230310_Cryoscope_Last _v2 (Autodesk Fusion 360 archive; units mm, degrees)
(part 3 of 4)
extrude "Extrude4" cut sketch "Sketch3" profile of L5 L6 L7 L8 against normal blind 100
sketch "Sketch4" plane through (0, 0, 1) normal (0, 0, -1) x axis (1, 0, 0)
  line L1 (0.5, -31.5) -> (23.5, -31.5)
  line L2 (0.5, -0.5) -> (0.5, -31.5)
  line L3 (23.5, -0.5) -> (0.5, -0.5)
  line L4 (23.5, -31.5) -> (23.5, -0.5)
  line L5 (-4, -63.5) -> (-4, 31.5)
  line L6 (28, -63.5) -> (-4, -63.5)
  line L7 (28, 31.5) -> (28, -63.5)
  line L8 (-4, 31.5) -> (28, 31.5)
  line L9 (23.5, -31.5) -> (0.5, -0.5)
  line L10 (23.5, -0.5) -> (0.5, -31.5)
  line L11 (24.25, -32.25) -> (-0.25, -32.25)
  line L12 (24.25, 0.25) -> (24.25, -32.25)
  line L13 (-0.25, 0.25) -> (24.25, 0.25)
  line L14 (-0.25, -32.25) -> (-0.25, 0.25)
  line L15 (24.25, 0.25) -> (-0.25, -32.25)
  line L16 (-0.25, 0.25) -> (24.25, -32.25)
  point P4 (0.5, -0.5)
  point P10 (0.5, -0.5)
  point P2 (23.5, -31.5)
  point P11 (23.5, -31.5)
  point P3 (0.5, -31.5)
  point P12 (0.5, -31.5)
  point P5 (23.5, -0.5)
  point P13 (23.5, -0.5)
  point P18 (12, -16)
  point P16 (24.25, 0.25)
  point P17 (-0.25, 0.25)
  point P15 (24.25, -32.25)
  coincident P4 P10
  coincident P2 P11
  coincident P3 P12
  coincident P5 P13
  horizontal L11
  perpendicular L11 L12
  parallel L11 L13
  parallel L12 L14
  coincident L15 P18
  coincident L16 P18
  midpoint L10 P18
  dimension "d15" distance P16 P17 = 24.5 (= "24 mm + 0.5 mm")
  dimension "d16" distance P15 P16 = 32.5
extrude "Extrude5" cut sketch "Sketch4" profile of L1 L2 L3 L4 L11 L12 L13 L14 against normal blind 0.5
move "Move1"
sketch "Sketch5" plane through (0, 63.5, 0) normal (0, 1, 0) x axis (-1, 0, 0)
  line L1 (-2.1851, -13.9322) -> (-24.8125, 8.6952)
  line L2 (-0.0638, -11.8109) -> (-2.1851, -13.9322)
  line L3 (-22.6912, 10.8165) -> (-0.0638, -11.8109)
  line L4 (-24.8125, 8.6952) -> (-22.6912, 10.8165)
  line L5 (-2.1851, -11.8109) -> (-0.0638, -11.8109)
  line L6 (-2.1851, -13.9322) -> (-2.1851, -11.8109)
  line L7 (-0.0638, -13.9322) -> (-2.1851, -13.9322)
  line L8 (-0.0638, -11.8109) -> (-0.0638, -13.9322)
  line L9 (-2.1851, -11.8109) -> (-0.0638, -11.8109)
  line L10 (-2.1851, -9.6896) -> (-2.1851, -11.8109)
  line L11 (-0.0638, -9.6896) -> (-2.1851, -9.6896)
  line L12 (-0.0638, -11.8109) -> (-0.0638, -9.6896)
  point P3 (-2.1851, -13.9322)
  point P8 (-2.1851, -13.9322)
  point P4 (-0.0638, -11.8109)
  point P6 (-0.0638, -11.8109)
  point P11 (-2.1851, -9.6896)
  horizontal L5
  vertical L6
  horizontal L7
  vertical L8
  coincident P3 P8
  coincident P4 P6
  horizontal L9
  vertical L10
  horizontal L11
  vertical L12
  coincident L3 P11
extrude "Extrude6" add sketch "Sketch5" profile of L2 L3 L7 L8 L11 L12 against normal blind 95
extrude "Extrude7" add of existing geometry blind 7.788 (= "10 mm - 2.212 mm")
extrude "Extrude8" add of existing geometry blind 0.91
extrude "Extrude9" cut of existing geometry blind -2
sketch "Sketch6" plane through (0, 0, -13.9322) normal (0, 0, -1) x axis (1, 0, 0)
  line L1 (2.1851, -63.5) -> (-8.6342, -63.5)
  line L2 (2.1851, 31.5) -> (2.1851, -63.5)
  line L3 (-8.6342, 31.5) -> (2.1851, 31.5)
  line L4 (-8.6342, -63.5) -> (-8.6342, 31.5)
  line L5 (10.0341, 31.5) -> (-8.6342, 31.5)
  line L6 (10.0341, -63.5) -> (10.0341, 31.5)
  line L7 (-8.6342, -63.5) -> (10.0341, -63.5)
  line L8 (-8.6342, 31.5) -> (-8.6342, -63.5)
  point P5 (-8.6342, 31.5)
  point P6 (-8.6342, 31.5)
  horizontal L5
  vertical L6
  horizontal L7
  vertical L8
  coincident P5 P6
extrude "Extrude10" cut sketch "Sketch6" against normal blind 1
extrude "Extrude11" cut of existing geometry blind -3
sketch "Sketch7" plane through (0, 0, -12.9322) normal (0, 0, -1) x axis (1, 0, 0)
  line L1 (-5.6342, -63.5) -> (-5.6342, 31.5)
  line L2 (3.1851, -63.5) -> (-5.6342, -63.5)
  line L3 (3.1851, 31.5) -> (3.1851, -63.5)
  line L4 (-5.6342, 31.5) -> (3.1851, 31.5)
  line L5 (3.1851, -63.5) -> (-5.6342, 31.5)
  line L6 (3.1851, 31.5) -> (-5.6342, -63.5)
  line L7 (-1.2245, 21.5) -> (-1.2245, -16)
  line L8 (-1.2245, -53.5) -> (-1.2245, -16)
  circle C1 centre (-1.2245, 21.5) radius 2.15
  circle C2 centre (-1.2245, -53.5) radius 2.15
  point P2 (-5.6342, 31.5)
  point P6 (-5.6342, 31.5)
  point P4 (3.1851, -63.5)
  point P7 (3.1851, -63.5)
  point P3 (-5.6342, -63.5)
  point P8 (-5.6342, -63.5)
  point P5 (3.1851, 31.5)
  point P9 (3.1851, 31.5)
  point P10 (-1.2245, -16)
  point P11 (-1.2245, 21.5)
  point P13 (-1.2245, 21.5)
  point P12 (-1.2245, -53.5)
  point P14 (-1.2245, -53.5)
  coincident P2 P6
  coincident P4 P7
  coincident P3 P8
  coincident P5 P9
  midpoint L5 P10
  perpendicular L4 L7
  parallel L3 L8
  coincident P11 P13
  coincident P12 P14
  dimension "d31" distance P10 P11 = 37.5 (= "( 75 / 2 ) * 1 mm")
  dimension "d32" distance P10 P12 = 37.5 (= "( 75 / 2 ) * 1 mm")
  dimension "d33" diameter C1 = 4.3
  dimension "d34" diameter C2 = 4.3
extrude "Extrude12" cut sketch "Sketch7" profile of C1 C2 against normal blind 100
extrude "Extrude13" add of existing geometry blind 1
sketch "Sketch8" plane through (-5.6342, 0, 0) normal (-1, 0, 0) x axis (0, -1, 0)
  line L1 (31.5, -12.9322) -> (-63.5, -12.9322)
  line L2 (31.5, -8.6896) -> (31.5, -12.9322)
  line L3 (-63.5, -8.6896) -> (31.5, -8.6896)
  line L4 (-63.5, -12.9322) -> (-63.5, -8.6896)
  line L5 (31.5, -8.6896) -> (-63.5, -8.6896)
  line L6 (-0.5, -8.6896) -> (31.5, -8.6896)
  line L7 (-0.5, -11.4518) -> (-0.5, -8.6896)
  line L8 (-31.5, -8.6896) -> (-63.5, -8.6896)
  line L9 (-31.5, -11) -> (-31.5, -8.6896)
  line L10 (-35, -10.4576) -> (-16, -10.4576)
  line L11 (6, -10.4576) -> (-16, -10.4576)
  point P5 (-63.5, -8.6896)
  point P6 (-63.5, -8.6896)
  point P4 (31.5, -8.6896)
  point P7 (31.5, -8.6896)
  point P9 (31.5, -8.6896)
  point P10 (-0.5, -8.6896)
  point P12 (-63.5, -8.6896)
  point P13 (-31.5, -8.6896)
  coincident P5 P6
  coincident P4 P7
  coincident P4 P9
  coincident L5 P10
  perpendicular L6 L7
  coincident P5 P12
  coincident L5 P13
  perpendicular L5 L9
  perpendicular L9 L10
  dimension "d40" distance P9 P10 = 32
  dimension "d41" distance P12 P13 = 32
extrude "Extrude14" cut sketch "Sketch8" profile of L3 L5 L7 L9 L10 L11 against normal blind 26
sketch "Sketch9" plane through (5.9373, 0, -5.9373) normal (-0.7071, 0, 0.7071) x axis (0, -1, 0)
  line L1 (-31.5, 19.1936) -> (-31.5, -3.8064)
  line L2 (-0.5, 19.1936) -> (-31.5, 19.1936)
  line L3 (-0.5, -3.8064) -> (-0.5, 19.1936)
  line L4 (-31.5, -3.8064) -> (-0.5, -3.8064)
  line L5 (-31.5, -3.8922) -> (-31.5, -5.3064)
  line L6 (-0.5, -3.8922) -> (-31.5, -3.8922)
  line L7 (-0.5, -5.3064) -> (-0.5, -3.8922)
  line L8 (31.5, -5.3064) -> (-0.5, -5.3064)
  line L9 (31.5, 21.6936) -> (31.5, -5.3064)
  line L10 (-63.5, 21.6936) -> (31.5, 21.6936)
  line L11 (-63.5, -5.3064) -> (-63.5, 21.6936)
  line L12 (-31.5, -5.3064) -> (-63.5, -5.3064)
  line L13 (-0.5, -4.5993) -> (-31.5, -4.5993)
  line L14 (-0.5, 19.1936) -> (-0.5, -4.5993)
  line L15 (-31.5, 19.1936) -> (-0.5, 19.1936)
  line L16 (-31.5, -4.5993) -> (-31.5, 19.1936)
  point P4 (-0.5, 19.1936)
  point P16 (-0.5, 19.1936)
  point P14 (-31.5, -4.5993)
  horizontal L13
  vertical L14
  horizontal L15
  vertical L16
  coincident P4 P16
  midpoint L5 P14
extrude "Extrude15" cut sketch "Sketch9" profile of L4 L6 L14 L16 against normal blind 10
delete_face "DeleteFace1"
delete_face "DeleteFace2"
sketch "Sketch10" plane through (0, -31.5, 0) normal (0, -1, 0) x axis (1, 0, 0)
  line L1 (-5.6342, -8.6896) -> (3.1851, -8.6896)
  line L2 (-5.6342, -12.9322) -> (-5.6342, -8.6896)
  line L3 (3.1851, -12.9322) -> (-5.6342, -12.9322)
  line L4 (23.3983, 7.281) -> (3.1851, -12.9322)
  line L5 (21.277, 9.4023) -> (23.3983, 7.281)
  line L6 (3.1851, -8.6896) -> (21.277, 9.4023)
  line L7 (10, 7.281) -> (23.3983, 7.281)
  point P6 (23.3983, 7.281)
  point P8 (23.3983, 7.281)
  coincident P6 P8
  horizontal L7
extrude "Extrude16" cut sketch "Sketch10" profile of L5 L6 L7 against normal blind 1000

design "MB3045_M-Step"
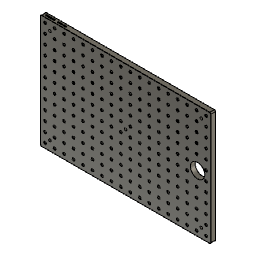
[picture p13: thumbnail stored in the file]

design "Zeiss_CMS_mount" references "Zeiss_stage_mount_430704-9910-000_01-001_asm"
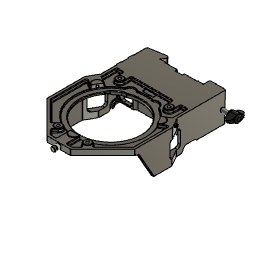
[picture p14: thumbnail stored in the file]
sketch "Sketch1" plane through (0, 0, 0) normal (0, 0, 1) x axis (1, 0, 0)
  line L1 (75.15, 31) -> (75.15, -31)
  line L2 (-75.15, -31) -> (-75.15, 31)
  line L3 (0, 0) -> (-47.9089, -19.7628)
  line L4 (-47.9089, 19.7628) -> (0, 0)
  line L5 (-65.65, 49) -> (-75.15, 31)
  line L6 (75.15, 31) -> (65.65, 49)
  line L7 (65.65, 74) -> (65.65, 49)
  line L8 (-65.65, 74) -> (65.65, 74)
  line L9 (-65.65, 49) -> (-65.65, 74)
  line L10 (16.15, -88) -> (-16.15, -88)
  line L11 (-75.15, -31) -> (-16.15, -88)
  line L12 (75.15, -31) -> (16.15, -88)
  circle C1 centre (0, 0) radius 51.825
  point P1 (0, 0)
  point P2 (0, 0)
  point P7 (0, 0)
  point P15 (-47.9089, -19.7628)
  point P16 (-47.9089, 19.7628)
  point P5 (75.15, 31)
  point P6 (-75.15, 31)
  point P4 (75.15, -31)
  point P8 (-65.65, 49)
  point P12 (-65.65, 74)
  coincident P1 P2
  parallel L1 L2
  coincident L3 P7
  coincident L4 P7
  coincident P2 P7
  vertical L7
  horizontal L8
  vertical L9
  coincident C1 P15
  coincident C1 P16
  dimension "d1" diameter C1 = 103.65
  dimension "d2" distance P5 P6 = 150.3
  dimension "d3" distance P4 P5 = 62
  dimension "d8" distance P8 P12 = 25
extrude "Extrude1" new body sketch "Sketch1" profile of C1 L1 L2 L5 L6 L7 L8 L9 L10 L11 L12 along normal blind 1
sketch "Sketch2" plane through (0, 0, 1) normal (0, 0, 1) x axis (-1, 0, 0)
  line L1 (-16.15, 88) -> (16.15, 88)
  line L2 (-75.15, 31) -> (-16.15, 88)
  line L3 (-75.15, -31) -> (-75.15, 31)
  line L4 (-65.65, -49) -> (-75.15, -31)
  line L5 (-65.65, -74) -> (-65.65, -49)
  line L6 (65.65, -74) -> (-65.65, -74)
  line L7 (65.65, -49) -> (65.65, -74)
  line L8 (75.15, -31) -> (65.65, -49)
  line L9 (75.15, 31) -> (75.15, -31)
  line L10 (16.15, 88) -> (75.15, 31)
  circle C1 centre (0, 0) radius 51.825
  circle C2 centre (0, 0) radius 60.5
  concentric C1 C2
  dimension "d15" diameter C2 = 121
extrude "Extrude2" add sketch "Sketch2" profile of L1 L2 L3 L4 L5 L6 L7 L8 L9 L10 C2 along normal blind 1.5
extrude "Extrude3" add of existing geometry blind 2.1
sketch "Sketch3" plane through (0, 0, 2.5) normal (0, 0, 1) x axis (-1, 0, 0)
  line L1 (16.15, 88) -> (75.15, 31)
  line L2 (-16.15, 88) -> (16.15, 88)
  line L3 (-75.15, 31) -> (-16.15, 88)
  line L4 (-75.15, -31) -> (-75.15, 31)
  line L5 (-65.65, -49) -> (-75.15, -31)
  line L6 (-65.65, -74) -> (-65.65, -49)
  line L7 (65.65, -74) -> (-65.65, -74)
  line L8 (65.65, -49) -> (65.65, -74)
  line L9 (75.15, -31) -> (65.65, -49)
  line L10 (75.15, 31) -> (75.15, -31)
  line L11 (-65.65, -49) -> (65.65, -49)
  line L12 (-65.65, -134.5) -> (-65.65, -49)
  line L13 (-38.05, -134.5) -> (-65.65, -134.5)
  line L14 (65.65, -49) -> (65.65, -128.4)
  line L15 (-38.05, -134.5) -> (-65.65, -134.5)
  line L16 (-38.05, -123.5) -> (-38.05, -134.5)
  line L17 (-27.65, -123.5) -> (-38.05, -123.5)
  line L18 (-27.65, -121.7) -> (-27.65, -123.5)
  line L19 (27.55, -121.7) -> (-27.65, -121.7)
  line L20 (27.55, -123.5) -> (27.55, -121.7)
  line L21 (36.45, -123.5) -> (27.55, -123.5)
  line L22 (36.45, -125.5) -> (36.45, -123.5)
  line L23 (34.45, -125.5) -> (36.45, -125.5)
  line L24 (31.25, -131.0426) -> (34.45, -125.5)
  line L25 (32.7519, -134.5) -> (31.25, -131.0426)
  line L26 (65.65, -128.4) -> (65.65, -49)
  line L27 (32.7519, -134.5) -> (65.65, -128.4)
  circle C1 centre (0, 0) radius 60.5
  point P11 (65.65, -49)
  point P13 (65.65, -49)
  point P26 (65.65, -49)
  point P14 (-65.65, -49)
  point P15 (-65.65, -134.5)
  point P16 (-38.05, -134.5)
  point P17 (-38.05, -123.5)
  point P18 (-27.65, -123.5)
  point P19 (-27.65, -121.7)
  point P21 (27.55, -123.5)
  point P22 (36.45, -123.5)
  point P23 (36.45, -125.5)
  point P24 (34.45, -125.5)
  point P25 (31.25, -131.0426)
  point P27 (65.65, -128.4)
  horizontal L11
  vertical L12
  horizontal L13
  vertical L14
  coincident P11 P13
  perpendicular L12 L15
  perpendicular L13 L16
  perpendicular L16 L17
  perpendicular L13 L18
  perpendicular L14 L19
  perpendicular L20 L21
  perpendicular L21 L22
  perpendicular L20 L23
  coincident P11 P26
  dimension "d20" distance P13 P14 = 131.3
  dimension "d22" distance P15 P16 = 27.6
  dimension "d23" distance P16 P17 = 11
  dimension "d24" distance P17 P18 = 10.4
  dimension "d25" distance P18 P19 = 1.8
  dimension "d27" distance P21 P22 = 8.9
  dimension "d28" distance P22 P23 = 2
  dimension "d29" distance P23 P24 = 2
  dimension "d30" angle L23 L24 = 120
  dimension "d31" distance P24 P25 = 6.4
  dimension "d32" distance P26 P27 = 79.4
extrude "Extrude4" add sketch "Sketch3" profile of L7 L12 L13 L14 L15 L16 L17 L18 L19 L20 L21 L22 L23 L24 L25 L26 L27 against normal blind 4.6
sketch "Sketch4" plane through (0, 0, 2.5) normal (0, 0, 1) x axis (-1, 0, 0)
  line L1 (16.15, 88) -> (75.15, 31)
  line L2 (-16.15, 88) -> (16.15, 88)
  line L3 (-75.15, 31) -> (-16.15, 88)
  line L4 (-75.15, -31) -> (-75.15, 31)
  line L5 (-65.65, -49) -> (-75.15, -31)
  line L6 (-65.65, -134.5) -> (-65.65, -49)
  line L7 (-38.05, -134.5) -> (-65.65, -134.5)
  line L8 (-38.05, -123.5) -> (-38.05, -134.5)
  line L9 (-27.65, -123.5) -> (-38.05, -123.5)
  line L10 (-27.65, -121.7) -> (-27.65, -123.5)
  line L11 (27.55, -121.7) -> (-27.65, -121.7)
  line L12 (27.55, -123.5) -> (27.55, -121.7)
  line L13 (36.45, -123.5) -> (27.55, -123.5)
  line L14 (36.45, -125.5) -> (36.45, -123.5)
  line L15 (34.45, -125.5) -> (36.45, -125.5)
  line L16 (31.25, -131.0426) -> (34.45, -125.5)
  line L17 (32.7519, -134.5) -> (31.25, -131.0426)
  line L18 (65.65, -128.4) -> (32.7519, -134.5)
  line L19 (65.65, -49) -> (65.65, -128.4)
  line L20 (75.15, -31) -> (65.65, -49)
  line L21 (75.15, 31) -> (75.15, -31)
  line L22 (-65.65, -73.5) -> (-65.65, -134.5)
  line L23 (65.65, -73.5) -> (-65.65, -73.5)
  circle C1 centre (0, 0) radius 60.5
  point P9 (-65.65, -134.5)
  point P24 (-65.65, -134.5)
  point P25 (-65.65, -73.5)
  point P26 (65.65, -73.5)
  coincident P9 P24
  coincident L6 P25
  coincident L19 P26
  perpendicular L19 L23
  dimension "d35" distance P24 P25 = 61
extrude "Extrude5" add sketch "Sketch4" profile of L6 L7 L8 L9 L10 L11 L12 L13 L14 L15 L16 L17 L18 L19 L22 L23 against normal blind 51.2
sketch "Sketch5" plane through (0, 0, 2.5) normal (0, 0, 1) x axis (-1, 0, 0)
  line L1 (65.65, -49) -> (65.65, -128.4)
  line L2 (75.15, -31) -> (65.65, -49)
  line L3 (75.15, 31) -> (75.15, -31)
  line L4 (16.15, 88) -> (75.15, 31)
  line L5 (-16.15, 88) -> (16.15, 88)
  line L6 (-75.15, 31) -> (-16.15, 88)
  line L7 (-75.15, -31) -> (-75.15, 31)
  line L8 (-65.65, -49) -> (-75.15, -31)
  line L9 (-65.65, -134.5) -> (-65.65, -49)
  line L10 (-38.05, -134.5) -> (-65.65, -134.5)
  line L11 (-38.05, -123.5) -> (-38.05, -134.5)
  line L12 (-27.65, -123.5) -> (-38.05, -123.5)
  line L13 (-27.65, -121.7) -> (-27.65, -123.5)
  line L14 (27.55, -121.7) -> (-27.65, -121.7)
  line L15 (27.55, -123.5) -> (27.55, -121.7)
  line L16 (36.45, -123.5) -> (27.55, -123.5)
  line L17 (36.45, -125.5) -> (36.45, -123.5)
  line L18 (34.45, -125.5) -> (36.45, -125.5)
  line L19 (31.25, -131.0426) -> (34.45, -125.5)
  line L20 (32.7519, -134.5) -> (31.25, -131.0426)
  line L21 (65.65, -128.4) -> (32.7519, -134.5)
  line L22 (60.15, -73.5) -> (-60.15, -73.5)
  line L23 (-13.9272, 82.5) -> (13.9272, 82.5)
  line L24 (-69.65, 28.6661) -> (-13.9272, 82.5)
  line L25 (-69.65, -29.6377) -> (-69.65, 28.6661)
  line L26 (-60.15, -47.6377) -> (-69.65, -29.6377)
  line L27 (-60.15, -73.5) -> (-60.15, -47.6377)
  line L28 (-33.15, -116.2) -> (-33.15, -118)
  line L29 (60.15, -47.6377) -> (60.15, -73.5)
  line L30 (69.65, -29.6377) -> (60.15, -47.6377)
  line L31 (69.65, 28.6661) -> (69.65, -29.6377)
  line L32 (13.9272, 82.5) -> (69.65, 28.6661)
  circle C1 centre (0, 0) radius 60.5
  perpendicular L1 L22
extrude "Extrude6" add sketch "Sketch5" profile of L1 L2 L3 L4 L5 L6 L7 L8 L9 L10 L11 L12 L13 L14 L15 L16 L17 L18 L19 L20 L21 L22 L25 L23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 along normal blind 5.1
extrude "Extrude7" cut of existing geometry blind -5.1
sketch "Sketch6" plane through (0, 0, -2.1) normal (0, 0, -1) x axis (1, 0, 0)
  line L1 (65.65, -73.5) -> (-65.65, -73.5)
  line L2 (65.65, -49) -> (65.65, -73.5)
  line L3 (75.15, -31) -> (65.65, -49)
  line L4 (75.15, 31) -> (75.15, -31)
  line L5 (16.15, 88) -> (75.15, 31)
  line L6 (-16.15, 88) -> (16.15, 88)
  line L7 (-75.15, 31) -> (-16.15, 88)
  line L8 (-75.15, -31) -> (-75.15, 31)
  line L9 (-65.65, -49) -> (-75.15, -31)
  line L10 (-65.65, -73.5) -> (-65.65, -49)
  line L11 (-61.35, -69.2) -> (-61.35, -47.9349)
  line L12 (61.35, -47.9349) -> (61.35, -69.2)
  line L13 (70.85, -29.9349) -> (61.35, -47.9349)
  line L14 (70.85, 29.1753) -> (70.85, -29.9349)
  line L15 (-70.85, -29.9349) -> (-70.85, 29.1753)
  line L16 (-61.35, -47.9349) -> (-70.85, -29.9349)
  line L17 (-61.35, -80) -> (-61.35, -69.2)
  line L18 (61.35, -80) -> (61.35, -69.2)
  line L19 (75.15, 24) -> (-75.15, 24)
  circle C1 centre (0, 0) radius 51.825
  point P6 (75.15, 31)
  point P24 (75.15, 24)
  perpendicular L1 L17
  horizontal L19
  dimension "d45" distance P6 P24 = 7
extrude "Extrude8" add sketch "Sketch6" profile of L1 L2 L3 L4 L8 L9 L10 L11 L14 L12 L13 L15 L16 L17 L18 L19 along normal blind 41.5
sketch "Sketch7" plane through (0, 0, -43.6) normal (0, 0, -1) x axis (1, 0, 0)
  line L1 (65.65, -134.5) -> (38.05, -134.5)
  line L2 (65.65, -49) -> (65.65, -134.5)
  line L3 (75.15, -31) -> (65.65, -49)
  line L4 (75.15, 24) -> (75.15, -31)
  line L5 (70.85, 24) -> (75.15, 24)
  line L6 (70.85, -29.9349) -> (70.85, 24)
  line L7 (61.35, -47.9349) -> (70.85, -29.9349)
  line L8 (61.35, -73.5) -> (61.35, -47.9349)
  line L9 (-61.35, -73.5) -> (61.35, -73.5)
  line L10 (-61.35, -47.9349) -> (-61.35, -73.5)
  line L11 (-70.85, -29.9349) -> (-61.35, -47.9349)
  line L12 (-70.85, 24) -> (-70.85, -29.9349)
  line L13 (-75.15, 24) -> (-70.85, 24)
  line L14 (-75.15, -31) -> (-75.15, 24)
  line L15 (-65.65, -49) -> (-75.15, -31)
  line L16 (-65.65, -128.4) -> (-65.65, -49)
  line L17 (-32.7519, -134.5) -> (-65.65, -128.4)
  line L18 (-31.25, -131.0426) -> (-32.7519, -134.5)
  line L19 (-34.45, -125.5) -> (-31.25, -131.0426)
  line L20 (-36.45, -125.5) -> (-34.45, -125.5)
  line L21 (-36.45, -123.5) -> (-36.45, -125.5)
  line L22 (-27.55, -123.5) -> (-36.45, -123.5)
  line L23 (-27.55, -121.7) -> (-27.55, -123.5)
  line L24 (27.65, -121.7) -> (-27.55, -121.7)
  line L25 (27.65, -123.5) -> (27.65, -121.7)
  line L26 (38.05, -123.5) -> (27.65, -123.5)
  line L27 (38.05, -134.5) -> (38.05, -123.5)
  line L28 (65.65, -63.5) -> (65.65, -134.5)
  line L29 (-90, -63.5) -> (65.65, -63.5)
  point P3 (65.65, -134.5)
  point P29 (65.65, -134.5)
  point P30 (65.65, -63.5)
  coincident P3 P29
  perpendicular L1 L28
  perpendicular L8 L29
  dimension "d48" distance P29 P30 = 71
extrude "Extrude9" add sketch "Sketch7" profile of L2 L3 L4 L5 L6 L7 L8 L10 L11 L12 L13 L14 L15 L16 L29 along normal blind 5.8
chamfer "Chamfer1" distance 2
fillet "Fillet1" radius 4
sketch "Sketch8" plane through (0, 0, 2.5) normal (0, 0, 1) x axis (-1, 0, 0)
  line L1 (-13.9272, 82.5) -> (13.9272, 82.5)
  line L2 (-69.65, 28.6661) -> (-13.9272, 82.5)
  line L3 (-69.65, -29.6377) -> (-69.65, 28.6661)
  line L4 (-60.15, -47.6377) -> (-69.65, -29.6377)
  line L5 (-60.15, -73.5) -> (-60.15, -47.6377)
  line L6 (60.15, -73.5) -> (-60.15, -73.5)
  line L7 (60.15, -47.6377) -> (60.15, -73.5)
  line L8 (69.65, -29.6377) -> (60.15, -47.6377)
  line L9 (69.65, 28.6661) -> (69.65, -29.6377)
  line L10 (13.9272, 82.5) -> (69.65, 28.6661)
  line L11 (13.9272, 82.5) -> (-13.9272, 82.5)
  line L12 (0, 82.5) -> (-13.9272, 82.5)
  line L13 (-9.25, 55.4108) -> (9.25, 55.4108)
  line L14 (-9.25, 109.5892) -> (-9.25, 55.4108)
  line L15 (9.25, 109.5892) -> (-9.25, 109.5892)
  line L16 (9.25, 55.4108) -> (9.25, 109.5892)
  line L17 (-9.25, 109.5892) -> (9.25, 55.4108)
  line L18 (9.25, 109.5892) -> (-9.25, 55.4108)
  circle C1 centre (0, 0) radius 60.5
  point P3 (-13.9272, 82.5)
  point P13 (-13.9272, 82.5)
  point P2 (13.9272, 82.5)
  point P14 (13.9272, 82.5)
  point P15 (0, 82.5)
  point P20 (0, 82.5)
  point P18 (-9.25, 109.5892)
  point P19 (9.25, 109.5892)
  coincident P3 P13
  coincident P2 P14
  midpoint L1 P15
  horizontal L13
  perpendicular L13 L14
  parallel L13 L15
  parallel L14 L16
  coincident L17 P20
  coincident L18 P20
  coincident P15 P20
  dimension "d54" distance P18 P19 = 18.5
extrude "Extrude10" add sketch "Sketch8" profile of L1 C1 L11 L12 L14 L16 along normal blind 5.1
sketch "Sketch9" plane through (0, 0, 7.6) normal (0, 0, 1) x axis (-1, 0, 0)
  line L1 (69.65, 28.6661) -> (13.9272, 82.5)
  line L2 (69.65, -29.6377) -> (69.65, 28.6661)
  line L3 (60.15, -47.6377) -> (69.65, -29.6377)
  line L4 (60.15, -73.5) -> (60.15, -47.6377)
  line L5 (-60.15, -73.5) -> (60.15, -73.5)
  line L6 (-60.15, -47.6377) -> (-60.15, -73.5)
  line L7 (-69.65, -29.6377) -> (-60.15, -47.6377)
  line L8 (-69.65, 28.6661) -> (-69.65, -29.6377)
  line L9 (-13.9272, 82.5) -> (-69.65, 28.6661)
  line L10 (-9.25, 82.5) -> (-13.9272, 82.5)
  line L11 (-9.25, 59.7887) -> (-9.25, 82.5)
  line L12 (9.25, 82.5) -> (9.25, 59.7887)
  line L13 (13.9272, 82.5) -> (9.25, 82.5)
  line L14 (65.65, -128.4) -> (32.7519, -134.5)
  line L15 (65.65, -49) -> (65.65, -128.4)
  line L16 (75.15, -31) -> (65.65, -49)
  line L17 (75.15, 31) -> (75.15, -31)
  line L18 (16.15, 88) -> (75.15, 31)
  line L19 (-16.15, 88) -> (16.15, 88)
  line L20 (-75.15, 31) -> (-16.15, 88)
  line L21 (-75.15, -31) -> (-75.15, 31)
  line L22 (-65.65, -49) -> (-75.15, -31)
  line L23 (-65.65, -134.5) -> (-65.65, -49)
  line L24 (-38.05, -134.5) -> (-65.65, -134.5)
  line L25 (-38.05, -123.5) -> (-38.05, -134.5)
  line L26 (-27.65, -123.5) -> (-38.05, -123.5)
  line L27 (-27.65, -121.7) -> (-27.65, -123.5)
  line L28 (27.55, -121.7) -> (-27.65, -121.7)
  line L29 (27.55, -123.5) -> (27.55, -121.7)
  line L30 (36.45, -123.5) -> (27.55, -123.5)
  line L31 (36.45, -125.5) -> (36.45, -123.5)
  line L32 (34.45, -125.5) -> (36.45, -125.5)
  line L33 (31.25, -131.0426) -> (34.45, -125.5)
  line L34 (32.7519, -134.5) -> (31.25, -131.0426)
  line L35 (-20, 88) -> (0, 88)
  line L36 (20, 88) -> (0, 88)
  line L37 (75.15, 31) -> (20, 88)
  line L38 (12.2418, 88) -> (69.65, 28.6661)
  line L39 (-75.15, 31) -> (-20, 88)
  line L40 (-12.242, 88) -> (-20, 88)
  line L41 (-69.65, 28.6661) -> (-12.242, 88)
  line L42 (0, 82.5) -> (0, 88)
  line L43 (17.5633, 82.5) -> (0, 82.5)
  line L44 (-17.5635, 82.5) -> (0, 82.5)
  arc A1 centre (0, 0) radius 60.5 clockwise from (-9.25, 59.7887) to (9.25, 59.7887)
  point P38 (0, 88)
  point P21 (75.15, 31)
  point P41 (75.15, 31)
  point P3 (69.65, 28.6661)
  point P42 (69.65, 28.6661)
  point P43 (12.2418, 88)
  point P24 (-75.15, 31)
  point P44 (-75.15, 31)
  point P45 (-12.242, 88)
  point P10 (-69.65, 28.6661)
  point P46 (-69.65, 28.6661)
  point P48 (17.5633, 82.5)
  point P49 (-17.5635, 82.5)
  point P39 (-20, 88)
  point P40 (20, 88)
  point P47 (0, 82.5)
  midpoint L19 P38
  perpendicular L12 L35
  parallel L19 L36
  coincident P21 P41
  coincident P3 P42
  coincident L19 P43
  parallel L37 L38
  coincident P24 P44
  coincident L35 P45
  coincident P10 P46
  perpendicular L19 L42
  coincident L38 P48
  perpendicular L42 L43
  coincident L41 P49
  perpendicular L42 L44
  dimension "d57" distance P38 P39 = 20
  dimension "d58" distance P38 P40 = 20
  dimension "d59" distance P39 P45 = 7.758
  dimension "d60" distance P38 P47 = 5.5
extrude "Extrude11" cut sketch "Sketch9" profile of L1 L9 L38 L41 L43 L44 against normal blind 5.1
extrude "Extrude12" add sketch "Sketch9" profile of L18 L20 L35 L36 L37 L39 L40 against normal blind 9.7
sketch "Sketch10" plane through (0, 0, 2.5) normal (0, 0, 1) x axis (-1, 0, 0)
  line L1 (9.25, 59.7887) -> (9.25, 82.5)
  line L2 (-9.25, 82.5) -> (-9.25, 59.7887)
  line L3 (-17.5635, 82.5) -> (-9.25, 82.5)
  line L4 (-69.65, 28.6661) -> (-17.5635, 82.5)
  line L5 (-69.65, -29.6377) -> (-69.65, 28.6661)
  line L6 (-60.15, -47.6377) -> (-69.65, -29.6377)
  line L7 (-60.15, -73.5) -> (-60.15, -47.6377)
  line L8 (60.15, -73.5) -> (-60.15, -73.5)
  line L9 (60.15, -47.6377) -> (60.15, -73.5)
  line L10 (69.65, -29.6377) -> (60.15, -47.6377)
  line L11 (69.65, 28.6661) -> (69.65, -29.6377)
  line L12 (17.5633, 82.5) -> (69.65, 28.6661)
  line L13 (9.25, 82.5) -> (17.5633, 82.5)
  line L14 (25.9075, 73.8759) -> (17.5633, 82.5)
  line L15 (35.851, 63.5989) -> (25.9075, 73.8759)
  line L16 (20.0991, 58.3072) -> (30.8792, 68.7374)
  line L17 (9.25, 57.7591) -> (25.9075, 73.8759)
  line L18 (19.8269, 48.0949) -> (35.851, 63.5989)
  arc A1 centre (0, 0) radius 60.5 clockwise from (9.25, 59.7887) to (-9.25, 59.7887)
  circle C1 centre (25.2377, 63.2789) radius 7.15
  point P16 (17.5633, 82.5)
  point P17 (17.5633, 82.5)
  point P18 (25.9075, 73.8759)
  point P19 (35.851, 63.5989)
  point P20 (30.8792, 68.7374)
  point P21 (20.0991, 58.3072)
  coincident P16 P17
  coincident L12 P18
  coincident L12 P19
  midpoint L15 P20
  perpendicular L12 L16
  perpendicular L14 L17
  perpendicular L12 L18
  coincident P21 C1
  tangent L18 C1
  tangent L17 C1
  dimension "d65" distance P17 P18 = 12
  dimension "d66" distance P18 P19 = 14.3
  dimension "d67" distance P20 P21 = 15
extrude "Extrude13" add sketch "Sketch10" profile of L12 L15 L16 L17 L18 C1 along normal blind 5.1
sketch "Sketch11" plane through (0, 0, 2.5) normal (0, 0, 1) x axis (-1, 0, 0)
  line L1 (30.2094, 58.1404) -> (35.851, 63.5989)
  line L2 (25.9075, 73.8759) -> (20.2659, 68.4175)
  line L3 (17.5633, 82.5) -> (25.9075, 73.8759)
  line L4 (9.25, 82.5) -> (17.5633, 82.5)
  line L5 (9.25, 59.7887) -> (9.25, 82.5)
  line L6 (-9.25, 82.5) -> (-9.25, 59.7887)
  line L7 (-17.5635, 82.5) -> (-9.25, 82.5)
  line L8 (-69.65, 28.6661) -> (-17.5635, 82.5)
  line L9 (-69.65, -29.6377) -> (-69.65, 28.6661)
  line L10 (-60.15, -47.6377) -> (-69.65, -29.6377)
  line L11 (-60.15, -73.5) -> (-60.15, -47.6377)
  line L12 (60.15, -73.5) -> (-60.15, -73.5)
  line L13 (60.15, -47.6377) -> (60.15, -73.5)
  line L14 (69.65, -29.6377) -> (60.15, -47.6377)
  line L15 (69.65, 28.6661) -> (69.65, -29.6377)
  line L16 (35.851, 63.5989) -> (69.65, 28.6661)
  line L17 (-25.9076, 73.8759) -> (-17.5635, 82.5)
  line L18 (-35.8511, 63.5989) -> (-25.9076, 73.8759)
  line L19 (25.9075, 73.8759) -> (35.851, 63.5989)
  line L20 (25.2377, 63.2789) -> (30.8792, 68.7374)
  line L21 (-25.2737, 63.3137) -> (-30.8794, 68.7374)
  line L22 (-30.2454, 58.1752) -> (-35.8511, 63.5989)
  line L23 (-25.9076, 73.8759) -> (-35.8511, 63.5989)
  line L24 (-20.302, 68.4522) -> (-25.9076, 73.8759)
  arc A1 centre (25.2377, 63.2789) radius 7.15 clockwise from (30.2094, 58.1404) to (20.2659, 68.4175)
  arc A2 centre (0, 0) radius 60.5 clockwise from (9.25, 59.7887) to (-9.25, 59.7887)
  arc A3 centre (-25.2737, 63.3137) radius 7.15 clockwise from (-20.302, 68.4522) to (-30.4122, 68.2854)
  point P13 (-17.5635, 82.5)
  point P22 (-17.5635, 82.5)
  point P24 (-35.8511, 63.5989)
  point P2 (35.851, 63.5989)
  point P25 (35.851, 63.5989)
  point P6 (25.9075, 73.8759)
  point P26 (25.9075, 73.8759)
  point P27 (30.8792, 68.7374)
  point P5 (25.2377, 63.2789)
  point P28 (25.2377, 63.2789)
  point P29 (-30.8794, 68.7374)
  point P30 (-25.2737, 63.3137)
  point P31 (-25.2737, 63.3137)
  point P32 (-30.2454, 58.1752)
  point P34 (-30.4122, 68.2854)
  point P23 (-25.9076, 73.8759)
  coincident P13 P22
  parallel L8 L17
  coincident L8 P24
  coincident P2 P25
  coincident P6 P26
  midpoint L19 P27
  coincident P5 P28
  midpoint L18 P29
  perpendicular L8 L21
  coincident P30 P31
  coincident P32 A3
  tangent L22 A3
  tangent L24 A3
  coincident L21 P34
  dimension "d70" distance P22 P23 = 12
  dimension "d71" distance P23 P24 = 14.3
  dimension "d72" distance P29 P30 = 7.8
  dimension "d73" diameter A3 = 14.3 (= "( 7.15 * 2 ) * 1 mm")
extrude "Extrude14" add sketch "Sketch11" profile of L8 L18 L21 A3 L22 L23 L24 along normal blind 5.1
sketch "Sketch12" plane through (0, 0, 7.6) normal (0, 0, 1) x axis (-1, 0, 0)
  line L1 (25.9075, 73.8759) -> (17.5633, 82.5)
  line L2 (20.2659, 68.4175) -> (25.9075, 73.8759)
  line L3 (35.851, 63.5989) -> (30.2094, 58.1404)
  line L4 (69.65, 28.6661) -> (35.851, 63.5989)
  line L5 (69.65, -29.6377) -> (69.65, 28.6661)
  line L6 (60.15, -47.6377) -> (69.65, -29.6377)
  line L7 (60.15, -73.5) -> (60.15, -47.6377)
  line L8 (-60.15, -73.5) -> (60.15, -73.5)
  line L9 (-60.15, -47.6377) -> (-60.15, -73.5)
  line L10 (-69.65, -29.6377) -> (-60.15, -47.6377)
  line L11 (-69.65, 28.6661) -> (-69.65, -29.6377)
  line L12 (-35.8511, 63.5989) -> (-69.65, 28.6661)
  line L13 (-30.2454, 58.1752) -> (-35.8511, 63.5989)
  line L14 (-25.9076, 73.8759) -> (-20.302, 68.4522)
  line L15 (-17.5635, 82.5) -> (-25.9076, 73.8759)
  line L16 (-9.25, 82.5) -> (-17.5635, 82.5)
  line L17 (-9.25, 59.7887) -> (-9.25, 82.5)
  line L18 (9.25, 82.5) -> (9.25, 59.7887)
  line L19 (17.5633, 82.5) -> (9.25, 82.5)
  line L20 (65.65, -128.4) -> (32.7519, -134.5)
  line L21 (65.65, -49) -> (65.65, -128.4)
  line L22 (75.15, -31) -> (65.65, -49)
  line L23 (75.15, 31) -> (75.15, -31)
  line L24 (20, 88) -> (75.15, 31)
  line L25 (-20, 88) -> (20, 88)
  line L26 (-75.15, 31) -> (-20, 88)
  line L27 (-75.15, -31) -> (-75.15, 31)
  line L28 (-65.65, -49) -> (-75.15, -31)
  line L29 (-65.65, -134.5) -> (-65.65, -49)
  line L30 (-38.05, -134.5) -> (-65.65, -134.5)
  line L31 (-38.05, -123.5) -> (-38.05, -134.5)
  line L32 (-27.65, -123.5) -> (-38.05, -123.5)
  line L33 (-27.65, -121.7) -> (-27.65, -123.5)
  line L34 (27.55, -121.7) -> (-27.65, -121.7)
  line L35 (27.55, -123.5) -> (27.55, -121.7)
  line L36 (36.45, -123.5) -> (27.55, -123.5)
  line L37 (36.45, -125.5) -> (36.45, -123.5)
  line L38 (34.45, -125.5) -> (36.45, -125.5)
  line L39 (31.25, -131.0426) -> (34.45, -125.5)
  line L40 (32.7519, -134.5) -> (31.25, -131.0426)
  arc A1 centre (25.2377, 63.2789) radius 7.15 clockwise from (30.2094, 58.1404) to (20.2659, 68.4175)
  arc A2 centre (-25.2737, 63.3137) radius 7.15 clockwise from (-20.302, 68.4522) to (-30.2454, 58.1752)
  arc A3 centre (0, 0) radius 60.5 clockwise from (-9.25, 59.7887) to (9.25, 59.7887)
  circle C1 centre (25.2377, 63.2789) radius 2.4
  circle C2 centre (-25.2737, 63.3137) radius 2.4
  concentric A1 C1
  concentric A2 C2
  dimension "d76" diameter C1 = 4.8
  dimension "d77" diameter C2 = 4.8
extrude "Extrude15" cut sketch "Sketch12" profile of C1 C2 against normal blind 100
sketch "Sketch13" plane through (0, 0, 2.5) normal (0, 0, 1) x axis (-1, 0, 0)
  line L1 (-35.8511, 63.5989) -> (-30.2454, 58.1752)
  line L2 (-69.65, 28.6661) -> (-35.8511, 63.5989)
  line L3 (-69.65, -29.6377) -> (-69.65, 28.6661)
  line L4 (-60.15, -47.6377) -> (-69.65, -29.6377)
  line L5 (-60.15, -73.5) -> (-60.15, -47.6377)
  line L6 (60.15, -73.5) -> (-60.15, -73.5)
  line L7 (60.15, -47.6377) -> (60.15, -73.5)
  line L8 (69.65, -29.6377) -> (60.15, -47.6377)
  line L9 (69.65, 28.6661) -> (69.65, -29.6377)
  line L10 (35.851, 63.5989) -> (69.65, 28.6661)
  line L11 (30.2094, 58.1404) -> (35.851, 63.5989)
  line L12 (25.9075, 73.8759) -> (20.2659, 68.4175)
  line L13 (17.5633, 82.5) -> (25.9075, 73.8759)
  line L14 (9.25, 82.5) -> (17.5633, 82.5)
  line L15 (9.25, 59.7887) -> (9.25, 82.5)
  line L16 (-9.25, 82.5) -> (-9.25, 59.7887)
  line L17 (-17.5635, 82.5) -> (-9.25, 82.5)
  line L18 (-25.9076, 73.8759) -> (-17.5635, 82.5)
  line L19 (-20.302, 68.4522) -> (-25.9076, 73.8759)
  line L20 (68.5983, -31.6303) -> (60.15, -47.6377)
  line L21 (35.63, -14.2304) -> (68.5983, -31.6303)
  line L22 (31.2714, -32.3962) -> (60.15, -47.6377)
  line L23 (-68.5983, -31.6303) -> (-60.15, -47.6377)
  line L24 (-35.6382, -14.2347) -> (-68.5983, -31.6303)
  line L25 (-25.9532, -29.5893) -> (-60.15, -47.6377)
  arc A1 centre (25.2377, 63.2789) radius 7.15 clockwise from (30.2094, 58.1404) to (20.2659, 68.4175)
  arc A2 centre (0, 0) radius 60.5 clockwise from (9.25, 59.7887) to (-9.25, 59.7887)
  arc A3 centre (-25.2737, 63.3137) radius 7.15 clockwise from (-20.302, 68.4522) to (-30.2454, 58.1752)
  point P9 (60.15, -47.6377)
  point P27 (60.15, -47.6377)
  point P28 (68.5983, -31.6303)
  point P30 (60.15, -47.6377)
  point P6 (-60.15, -47.6377)
  point P32 (-60.15, -47.6377)
  point P33 (-68.5983, -31.6303)
  coincident P9 P27
  coincident L8 P28
  perpendicular L8 L21
  coincident P9 P30
  perpendicular L8 L22
  coincident P6 P32
  coincident L4 P33
  perpendicular L4 L24
  perpendicular L4 L25
  dimension "d80" distance P27 P28 = 18.1
  dimension "d81" distance P32 P33 = 18.1
extrude "Extrude16" add sketch "Sketch13" profile of L4 L8 A2 L20 L21 L22 L23 L24 L25 along normal blind 5.1
sketch "Sketch14" plane through (0, 0, 2.5) normal (0, 0, 1) x axis (-1, 0, 0)
  line L1 (-60.15, -47.6377) -> (-45.4815, -39.8959)
  line L2 (-60.15, -73.5) -> (-60.15, -47.6377)
  line L3 (60.15, -73.5) -> (-60.15, -73.5)
  line L4 (60.15, -47.6377) -> (60.15, -73.5)
  line L5 (45.4815, -39.8959) -> (60.15, -47.6377)
  line L6 (-49.55, -73.5) -> (-60.15, -73.5)
  line L7 (-34.95, -73.5) -> (-49.55, -73.5)
  line L8 (-42.25, -53) -> (-42.25, -73.5)
  line L9 (49.55, -73.5) -> (60.15, -73.5)
  line L10 (34.95, -73.5) -> (49.55, -73.5)
  line L11 (42.25, -53) -> (42.25, -73.5)
  line L12 (49.55, -73.5) -> (34.95, -73.5)
  line L13 (49.55, -53) -> (49.55, -73.5)
  line L14 (34.95, -53) -> (49.55, -53)
  line L15 (34.95, -73.5) -> (34.95, -53)
  line L16 (-34.95, -73.5) -> (-49.55, -73.5)
  line L17 (-34.95, -53) -> (-34.95, -73.5)
  line L18 (-49.55, -53) -> (-34.95, -53)
  line L19 (-49.55, -73.5) -> (-49.55, -53)
  line L20 (42.25, -60.3) -> (42.25, -53)
  line L21 (-42.25, -60.3) -> (-42.25, -53)
  arc A1 centre (0, 0) radius 60.5 clockwise from (45.4815, -39.8959) to (-45.4815, -39.8959)
  circle C1 centre (42.25, -60.3) radius 7.3
  circle C2 centre (-42.25, -60.3) radius 7.3
  point P4 (-60.15, -73.5)
  point P9 (-60.15, -73.5)
  point P10 (-49.55, -73.5)
  point P11 (-34.95, -73.5)
  point P12 (-42.25, -73.5)
  point P5 (60.15, -73.5)
  point P14 (60.15, -73.5)
  point P16 (34.95, -73.5)
  point P17 (42.25, -73.5)
  point P26 (-42.25, -60.3)
  point P25 (42.25, -60.3)
  point P27 (42.25, -60.3)
  point P28 (-42.25, -60.3)
  point P13 (-42.25, -53)
  point P15 (49.55, -73.5)
  point P18 (42.25, -53)
  point P21 (34.95, -53)
  point P24 (-49.55, -53)
  coincident P4 P9
  coincident L3 P10
  coincident L3 P11
  midpoint L7 P12
  perpendicular L7 L8
  coincident P5 P14
  perpendicular L4 L9
  coincident L3 P16
  midpoint L10 P17
  perpendicular L10 L11
  horizontal L12
  vertical L13
  horizontal L14
  vertical L15
  horizontal L16
  vertical L17
  horizontal L18
  vertical L19
  perpendicular L14 L20
  coincident L8 P26
  coincident P25 P27
  tangent L15 C1
  coincident P26 P28
  tangent L19 C2
  dimension "d84" distance P9 P10 = 10.6
  dimension "d85" distance P10 P11 = 14.6
  dimension "d86" distance P12 P13 = 20.5
  dimension "d87" distance P14 P15 = 10.6
  dimension "d88" distance P15 P16 = 14.6
  dimension "d89" distance P17 P18 = 20.5
  dimension "d90" distance P16 P21 = 20.5
  dimension "d91" distance P10 P24 = 20.5
  dimension "d92" distance P18 P25 = 7.3 (= "( 14.6 / 2 ) * 1 mm")
  dimension "d93" distance P13 P26 = 7.3 (= "( 14.6 / 2 ) * 1 mm")
extrude "Extrude17" add sketch "Sketch14" profile of L3 L7 L8 L10 L11 L12 L13 L15 L16 L17 L19 L20 L21 C1 C2 along normal blind 5.1
fillet "Fillet2" radius 1
fillet "Fillet3" radius 1
fillet "Fillet4" radius 1
sketch "Sketch15" plane through (0, 0, 7.6) normal (0, 0, 1) x axis (-1, 0, 0)
  line L1 (65.65, -128.4) -> (32.7519, -134.5)
  line L2 (65.65, -49) -> (65.65, -128.4)
  line L3 (75.15, -31) -> (65.65, -49)
  line L4 (75.15, 31) -> (75.15, -31)
  line L5 (20, 88) -> (75.15, 31)
  line L6 (-20, 88) -> (20, 88)
  line L7 (-75.15, 31) -> (-20, 88)
  line L8 (-75.15, -31) -> (-75.15, 31)
  line L9 (-65.65, -49) -> (-75.15, -31)
  line L10 (-65.65, -134.5) -> (-65.65, -49)
  line L11 (-38.05, -134.5) -> (-65.65, -134.5)
  line L12 (-38.05, -123.5) -> (-38.05, -134.5)
  line L13 (-27.65, -123.5) -> (-38.05, -123.5)
  line L14 (-27.65, -121.7) -> (-27.65, -123.5)
  line L15 (27.55, -121.7) -> (-27.65, -121.7)
  line L16 (27.55, -123.5) -> (27.55, -121.7)
  line L17 (36.45, -123.5) -> (27.55, -123.5)
  line L18 (36.45, -125.5) -> (36.45, -123.5)
  line L19 (34.45, -125.5) -> (36.45, -125.5)
  line L20 (31.25, -131.0426) -> (34.45, -125.5)
  line L21 (32.7519, -134.5) -> (31.25, -131.0426)
  line L22 (60.15, -46.5069) -> (46.1515, -39.1189)
  line L23 (60.15, -73.5) -> (60.15, -46.5069)
  line L24 (48.55, -73.5) -> (60.15, -73.5)
  line L25 (48.55, -60.3) -> (48.55, -73.5)
  line L26 (35.95, -73.5) -> (35.95, -60.3)
  line L27 (-35.95, -73.5) -> (35.95, -73.5)
  line L28 (-35.95, -60.3) -> (-35.95, -73.5)
  line L29 (-48.55, -73.5) -> (-48.55, -60.3)
  line L30 (-60.15, -73.5) -> (-48.55, -73.5)
  line L31 (-60.15, -46.5069) -> (-60.15, -73.5)
  line L32 (-46.1515, -39.1189) -> (-60.15, -46.5069)
  line L33 (-68.1316, -32.5147) -> (-54.859, -25.5097)
  line L34 (-69.65, -29.6377) -> (-68.1316, -32.5147)
  line L35 (-69.65, 28.6661) -> (-69.65, -29.6377)
  line L36 (-35.1558, 64.3175) -> (-69.65, 28.6661)
  line L37 (-29.5501, 58.8938) -> (-35.1558, 64.3175)
  line L38 (-26.603, 73.1572) -> (-20.9973, 67.7335)
  line L39 (-17.5635, 82.5) -> (-26.603, 73.1572)
  line L40 (-8.25, 82.5) -> (-17.5635, 82.5)
  line L41 (-8.25, 59.9349) -> (-8.25, 82.5)
  line L42 (8.25, 82.5) -> (8.25, 59.9349)
  line L43 (17.5633, 82.5) -> (8.25, 82.5)
  line L44 (26.6028, 73.1572) -> (17.5633, 82.5)
  line L45 (20.9613, 67.6988) -> (26.6028, 73.1572)
  line L46 (35.1556, 64.3176) -> (29.514, 58.8591)
  line L47 (69.65, 28.6661) -> (35.1556, 64.3176)
  line L48 (69.65, -29.6377) -> (69.65, 28.6661)
  line L49 (68.1316, -32.5147) -> (69.65, -29.6377)
  line L50 (54.859, -25.5097) -> (68.1316, -32.5147)
  circle C1 centre (25.2377, 63.2789) radius 2.4
  circle C2 centre (-25.2737, 63.3137) radius 2.4
  arc A1 centre (42.25, -60.3) radius 6.3 clockwise from (35.95, -60.3) to (48.55, -60.3)
  arc A2 centre (-42.25, -60.3) radius 6.3 clockwise from (-48.55, -60.3) to (-35.95, -60.3)
  arc A3 centre (0, 0) radius 60.5 clockwise from (-46.1515, -39.1189) to (-54.859, -25.5097)
  arc A4 centre (-25.2737, 63.3137) radius 6.15 clockwise from (-20.9973, 67.7335) to (-29.5501, 58.8938)
  arc A5 centre (0, 0) radius 60.5 clockwise from (-8.25, 59.9349) to (8.25, 59.9349)
  arc A6 centre (25.2377, 63.2789) radius 6.15 clockwise from (29.514, 58.8591) to (20.9613, 67.6988)
  arc A7 centre (0, 0) radius 60.5 clockwise from (54.859, -25.5097) to (46.1515, -39.1189)
  circle C3 centre (42.25, -60.3) radius 2.4
  circle C4 centre (-42.25, -60.3) radius 2.4
  concentric A1 C3
  concentric A2 C4
  dimension "d102" diameter C3 = 4.8
  dimension "d103" diameter C4 = 4.8
extrude "Extrude18" cut sketch "Sketch15" profile of C3 C4 against normal blind 100
sketch "Sketch16" plane through (0, 0, 7.6) normal (0, 0, 1) x axis (-1, 0, 0)
  line L1 (65.65, -128.4) -> (32.7519, -134.5)
  line L2 (65.65, -49) -> (65.65, -128.4)
  line L3 (75.15, -31) -> (65.65, -49)
  line L4 (75.15, 31) -> (75.15, -31)
  line L5 (20, 88) -> (75.15, 31)
  line L6 (-20, 88) -> (20, 88)
  line L7 (-75.15, 31) -> (-20, 88)
  line L8 (-75.15, -31) -> (-75.15, 31)
  line L9 (-65.65, -49) -> (-75.15, -31)
  line L10 (-65.65, -134.5) -> (-65.65, -49)
  line L11 (-38.05, -134.5) -> (-65.65, -134.5)
  line L12 (-38.05, -123.5) -> (-38.05, -134.5)
  line L13 (-27.65, -123.5) -> (-38.05, -123.5)
  line L14 (-27.65, -121.7) -> (-27.65, -123.5)
  line L15 (27.55, -121.7) -> (-27.65, -121.7)
  line L16 (27.55, -123.5) -> (27.55, -121.7)
  line L17 (36.45, -123.5) -> (27.55, -123.5)
  line L18 (36.45, -125.5) -> (36.45, -123.5)
  line L19 (34.45, -125.5) -> (36.45, -125.5)
  line L20 (31.25, -131.0426) -> (34.45, -125.5)
  line L21 (32.7519, -134.5) -> (31.25, -131.0426)
  line L22 (60.15, -46.5069) -> (46.1515, -39.1189)
  line L23 (60.15, -73.5) -> (60.15, -46.5069)
  line L24 (48.55, -73.5) -> (60.15, -73.5)
  line L25 (48.55, -60.3) -> (48.55, -73.5)
  line L26 (35.95, -73.5) -> (35.95, -60.3)
  line L27 (-35.95, -73.5) -> (35.95, -73.5)
  line L28 (-35.95, -60.3) -> (-35.95, -73.5)
  line L29 (-48.55, -73.5) -> (-48.55, -60.3)
  line L30 (-60.15, -73.5) -> (-48.55, -73.5)
  line L31 (-60.15, -46.5069) -> (-60.15, -73.5)
  line L32 (-46.1515, -39.1189) -> (-60.15, -46.5069)
  line L33 (-68.1316, -32.5147) -> (-54.859, -25.5097)
  line L34 (-69.65, -29.6377) -> (-68.1316, -32.5147)
  line L35 (-69.65, 28.6661) -> (-69.65, -29.6377)
  line L36 (-35.1558, 64.3175) -> (-69.65, 28.6661)
  line L37 (-29.5501, 58.8938) -> (-35.1558, 64.3175)
  line L38 (-26.603, 73.1572) -> (-20.9973, 67.7335)
  line L39 (-17.5635, 82.5) -> (-26.603, 73.1572)
  line L40 (-8.25, 82.5) -> (-17.5635, 82.5)
  line L41 (-8.25, 59.9349) -> (-8.25, 82.5)
  line L42 (8.25, 82.5) -> (8.25, 59.9349)
  line L43 (17.5633, 82.5) -> (8.25, 82.5)
  line L44 (26.6028, 73.1572) -> (17.5633, 82.5)
  line L45 (20.9613, 67.6988) -> (26.6028, 73.1572)
  line L46 (35.1556, 64.3176) -> (29.514, 58.8591)
  line L47 (69.65, 28.6661) -> (35.1556, 64.3176)
  line L48 (69.65, -29.6377) -> (69.65, 28.6661)
  line L49 (68.1316, -32.5147) -> (69.65, -29.6377)
  line L50 (54.859, -25.5097) -> (68.1316, -32.5147)
  circle C1 centre (42.25, -60.3) radius 2.4
  circle C2 centre (-42.25, -60.3) radius 2.4
  circle C3 centre (25.2377, 63.2789) radius 2.4
  circle C4 centre (-25.2737, 63.3137) radius 2.4
  arc A1 centre (42.25, -60.3) radius 6.3 clockwise from (35.95, -60.3) to (48.55, -60.3)
  arc A2 centre (-42.25, -60.3) radius 6.3 clockwise from (-48.55, -60.3) to (-35.95, -60.3)
  arc A3 centre (0, 0) radius 60.5 clockwise from (-46.1515, -39.1189) to (-54.859, -25.5097)
  arc A4 centre (-25.2737, 63.3137) radius 6.15 clockwise from (-20.9973, 67.7335) to (-29.5501, 58.8938)
  arc A5 centre (0, 0) radius 60.5 clockwise from (-8.25, 59.9349) to (8.25, 59.9349)
  arc A6 centre (25.2377, 63.2789) radius 6.15 clockwise from (29.514, 58.8591) to (20.9613, 67.6988)
  arc A7 centre (0, 0) radius 60.5 clockwise from (54.859, -25.5097) to (46.1515, -39.1189)
  circle C5 centre (42.25, -60.3) radius 5.5
  circle C6 centre (-42.25, -60.3) radius 5.5
  circle C7 centre (-25.2737, 63.3137) radius 5.5
  circle C8 centre (25.2377, 63.2789) radius 5.5
  circle C9 centre (0, 60.5) radius 7.5
  circle C10 centre (50.9616, -32.6062) radius 7.5
  circle C11 centre (-50.9616, -32.6062) radius 7.5
  point P68 (0, 60.5)
  point P69 (50.9616, -32.6062)
  point P70 (-50.9616, -32.6062)
  concentric C1 C5
  concentric C2 C6
  concentric C4 C7
  concentric C3 C8
  midpoint A5 P68
  midpoint A7 P69
  midpoint A3 P70
  dimension "d106" diameter C5 = 11
  dimension "d107" diameter C6 = 11
  dimension "d108" diameter C7 = 11
  dimension "d109" diameter C8 = 11
  dimension "d110" diameter C9 = 15
  dimension "d111" diameter C10 = 15
  dimension "d112" diameter C11 = 15
extrude "Extrude19" new body sketch "Sketch16" profile of C1 C2 C3 C4 A3 A5 A7 C5 C6 C7 C8 C9 C10 C11 along normal blind 0.3
combine "Combine1"
sketch "Sketch17" plane through (0, -88, 0) normal (0, -1, 0) x axis (1, 0, 0)
  line L1 (-20, 7.6) -> (20, 7.6)
  line L2 (-20, -2.1) -> (-20, 7.6)
  line L3 (20, -2.1) -> (-20, -2.1)
  line L4 (20, 7.6) -> (20, -2.1)
  line L5 (0, -2.1) -> (0, 7.6)
  circle C1 centre (0, 2.75) radius 4.05
  point P6 (0, 7.6)
  point P7 (0, -2.1)
  point P8 (0, 2.75)
  midpoint L1 P6
  midpoint L3 P7
  midpoint L5 P8
  dimension "d115" diameter C1 = 8.1
extrude "Extrude20" new body sketch "Sketch17" profile of L5 C1 along normal blind 9.3
chamfer "Chamfer2" distance 1
sketch "Sketch18" plane through (0, -97.3, 0) normal (0, -1, 0) x axis (1, 0, 0)
  circle C1 centre (0, 2.75) radius 3.05
  circle C2 centre (0, 2.75) radius 2
  concentric C1 C2
  dimension "d119" diameter C2 = 4
extrude "Extrude21" new body sketch "Sketch18" profile of C2 along normal blind 10
chamfer "Chamfer3" distance 1 distance 4.5
fillet "Fillet5" radius 1
move "Move1"
move "Move2"
move "Move3" TranslateX 0 TranslateY 33 TranslateZ 0
sketch "Sketch19" plane through (71.5742, 37.7753, 0) normal (0.8844, 0.4668, 0) x axis (-0.4668, 0.8844, 0)
  line L1 (12.6921, 7.6) -> (12.6921, -49.4)
  line L2 (-7.661, 7.6) -> (12.6921, 7.6)
  line L3 (-7.661, -49.4) -> (-7.661, 7.6)
  line L4 (12.6921, -49.4) -> (-7.661, -49.4)
  circle C1 centre (5, 5) radius 2
  dimension "d129" diameter C1 = 4
extrude "Extrude22" new body sketch "Sketch19" profile of C1 along normal blind 2
fillet "Fillet6" radius 2
move "Move4"
move "Move5"
move "Move6"
move "Move7"
copy_paste_bodies "CopyPasteBodies1"
move "Move8"
move "Move9"
move "Move10"
sketch "Sketch20" plane through (65.65, 0, 0) normal (1, 0, 0) x axis (0, 1, 0)
  line L1 (63.5, -47.4) -> (61.5, -49.4)
  line L2 (134.5, -43.6) -> (67.495, -43.6)
  line L3 (134.5, 7.6) -> (134.5, -43.6)
  line L4 (49, 7.6) -> (134.5, 7.6)
  line L5 (49, -49.4) -> (49, 7.6)
  line L6 (61.5, -49.4) -> (49, -49.4)
  line L7 (134.5, 7.6) -> (134.5, -43.6)
  line L8 (127.5, -18) -> (134.5, -18)
  arc A1 centre (67.495, -47.6) radius 4 clockwise from (63.5, -47.4) to (67.495, -43.6)
  circle C1 centre (127.5, -18) radius 3.5
  point P6 (134.5, -43.6)
  point P10 (134.5, -43.6)
  point P7 (134.5, 7.6)
  point P11 (134.5, 7.6)
  point P12 (134.5, -18)
  point P13 (127.5, -18)
  point P14 (127.5, -18)
  coincident P6 P10
  coincident P7 P11
  midpoint L3 P12
  perpendicular L3 L8
  coincident P13 P14
  dimension "d134" distance P12 P13 = 7
  dimension "d135" diameter C1 = 7
extrude "Extrude23" new body sketch "Sketch20" profile of C1 along normal blind 15.2
sketch "Sketch21" plane through (80.85, 0, 0) normal (1, 0, 0) x axis (0, 1, 0)
  line L1 (113.6, -16) -> (113.6, -18)
  line L2 (141.4, -20) -> (141.4, -17)
  line L3 (113.6, -16) -> (113.6, -19)
  line L4 (124.1746, -10.9863) -> (113.6, -16)
  line L5 (130.8254, -25.0137) -> (141.4, -20)
  line L6 (140.4, -16) -> (138.698, -16)
  line L7 (114.6, -20) -> (116.302, -20)
  circle C1 centre (127.5, -18) radius 3.5
  arc A1 centre (127.5, -18) radius 7.7621 clockwise from (124.1746, -10.9863) to (133.8159, -13.4878)
  arc A2 centre (127.5, -18) radius 7.7621 clockwise from (130.8254, -25.0137) to (121.1841, -22.5122)
  arc A3 centre (138.698, -10) radius 6 clockwise from (138.698, -16) to (133.8159, -13.4878)
  arc A4 centre (116.302, -26) radius 6 clockwise from (116.302, -20) to (121.1841, -22.5122)
  arc A5 centre (114.6, -19) radius 1 clockwise from (114.6, -20) to (113.6, -19)
  arc A6 centre (140.4, -17) radius 1 clockwise from (140.4, -16) to (141.4, -17)
  point P7 (113.6, -20)
  point P3 (127.5, -18)
  point P4 (113.6, -18)
  point P5 (113.6, -16)
  concentric C1 A1
  vertical L2
  vertical L3
  tangent L4 A1
  tangent L5 A1
  parallel L4 L5
  concentric A1 A2
  tangent L6 A3
  tangent A1 A3
  tangent L7 A4
  tangent A2 A4
  equal A3 A4
  coincident P7 L3
  coincident P7 L7
  tangent L3 A5
  tangent L7 A5
  tangent L2 A6
  tangent L6 A6
  equal A5 A6
  dimension "d138" distance P3 P4 = 13.9 (= "( 27.8 / 2 ) * 1 mm")
  dimension "d140" distance P4 P5 = 2
  dimension "d141" distance P5 P7 = 4
  dimension "d142" radius A3 = 6
  dimension "d143" radius A5 = 1
extrude "Extrude24" new body sketch "Sketch21" profile of C1 A2 L1 L6 L2 L7 L3 L4 L5 A3 A4 A5 A6 along normal blind 14
chamfer "Chamfer4" distance 1
chamfer "Chamfer5" distance 1
sketch "Sketch22" plane through (80.85, 0, 0) normal (-1, 0, 0) x axis (0, -1, 0)
  line L1 (-124.603, -11.8899) -> (-114.6, -16.6326)
  line L2 (-140.4, -17) -> (-138.698, -17)
  line L3 (-140.4, -19.3674) -> (-140.4, -17)
  line L4 (-130.397, -24.1101) -> (-140.4, -19.3674)
  line L5 (-114.6, -19) -> (-116.302, -19)
  line L6 (-114.6, -16.6326) -> (-114.6, -19)
  arc A1 centre (-127.5, -18) radius 6.7621 clockwise from (-133.0022, -14.0692) to (-124.603, -11.8899)
  arc A2 centre (-138.698, -10) radius 7 clockwise from (-133.0022, -14.0692) to (-138.698, -17)
  arc A3 centre (-127.5, -18) radius 6.7621 clockwise from (-121.9978, -21.9308) to (-130.397, -24.1101)
  arc A4 centre (-116.302, -26) radius 7 clockwise from (-121.9978, -21.9308) to (-116.302, -19)
  circle C1 centre (-127.5, -18) radius 5.762
  concentric A1 C1
  dimension "d148" diameter C1 = 11.524 (= "13.524 mm - 2 mm")
extrude "Extrude25" add sketch "Sketch22" profile of C1 along normal blind 1
component_insert "Component Insert"
chamfer "Chamfer6" distance 23 distance 47
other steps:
base_feature "Base Feature"

design "BOOMELE(Boom Precision Elec) C32896"
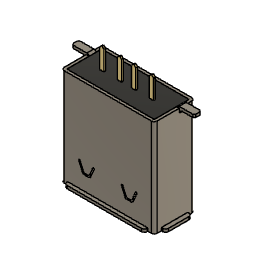
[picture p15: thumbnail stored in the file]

design "Connector_Ass_Step"
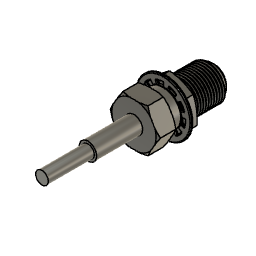
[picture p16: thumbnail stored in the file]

design "LED_G"
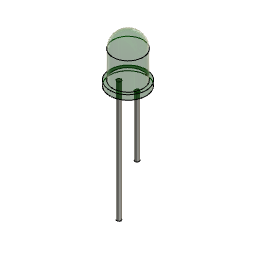
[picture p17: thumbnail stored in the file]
sketch "Sketch1" plane through (0, 0, 0) normal (0, 0, 1) x axis (1, 0, 0)
  circle C1 centre (0, 0) radius 3
  point P1 (0, 0)
  point P2 (0, 0)
  coincident P1 P2
  dimension "d1" diameter C1 = 6
extrude "Extrude1" new body sketch "Sketch1" along normal blind 0.8
sketch "Sketch2" plane through (0, 0, 0.8) normal (0, 0, 1) x axis (-1, 0, 0)
  circle C1 centre (0, 0) radius 3
  circle C2 centre (0, 0) radius 2.5
  point P1 (0, 0)
  point P3 (0, 0)
  coincident P1 P3
extrude "Extrude2" add sketch "Sketch2" profile of C2 along normal blind 7
fillet "Fillet1" radius 2.5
